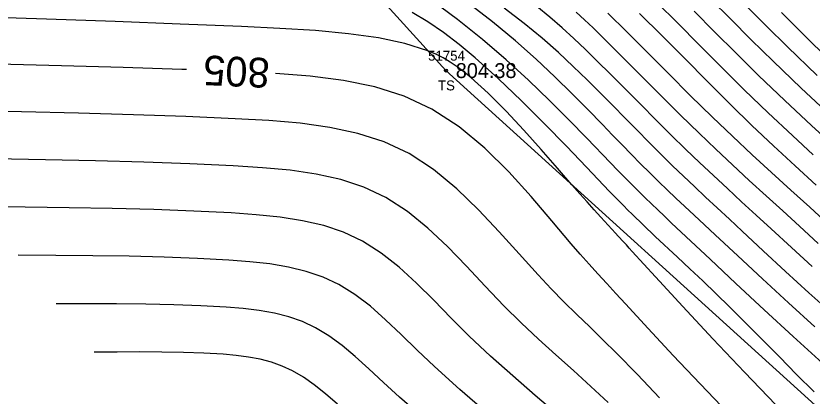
# Model space of a CAD drawing. Extents: x 1378535 to 1380697, y 997729 to 1000024.
# Drawn here: x 1379772.3 to 1379852.8, y 998705.8 to 998744.2 of the extents above; entities that cross this region are included whole.
import ezdxf

# ---------------------------------------------------------------- set-up
doc = ezdxf.new("R2010")
doc.units = 0
for name, color, linetype in [('RD_DTM_BkLn2', 7, 'Continuous'), ('RD_DTM_BkLn_txCode', 7, 'Continuous'), ('RD_DTM_Major1', 7, 'Continuous'), ('RD_DTM_Major1_Lbl', 7, 'Continuous'), ('RD_DTM_Minor1', 7, 'Continuous'), ('RD_EX_TX_Misc_ELEV', 7, 'Continuous'), ('RD_SMD_Locator', 7, 'Continuous')]:
    doc.layers.add(name, color=color, linetype=linetype)

msp = doc.modelspace()

# ---------------------------------------------------------------- linework, layer by layer
at = {"layer": 'RD_DTM_BkLn2'}
msp.add_lwpolyline([(1379855.611, 998702.628), (1379815.746, 998738.674), (1379770.168, 998788.836), (1379745.983, 998819.459), (1379725.877, 998843.791)], dxfattribs=at)
at = {"layer": 'RD_DTM_Major1'}
for points in [[(1379852.883, 998730.183), (1379850.774, 998732.118), (1379848.323, 998734.413), (1379845.901, 998736.737), (1379843.591, 998739.014), (1379841.35, 998741.263), (1379839.179, 998743.452), (1379837.08, 998745.549)], [(1379854.843, 998714.093), (1379852.439, 998716.234), (1379850.089, 998718.385), (1379847.829, 998720.486), (1379845.696, 998722.477), (1379844.411, 998723.672), (1379843.183, 998724.81), (1379842.004, 998725.906), (1379840.864, 998726.972), (1379839.753, 998728.023), (1379838.664, 998729.072), (1379837.463, 998730.251), (1379836.268, 998731.445), (1379835.07, 998732.656), (1379833.861, 998733.885), (1379832.63, 998735.135), (1379831.371, 998736.407), (1379830.036, 998737.737), (1379828.629, 998739.098), (1379827.119, 998740.498), (1379825.475, 998741.942), (1379823.664, 998743.438), (1379821.655, 998744.991)], [(1379789.535, 998738.772), (1379789.073, 998738.791), (1379783.125, 998738.99), (1379776.896, 998739.168), (1379770.455, 998739.331), (1379763.873, 998739.484), (1379757.22, 998739.632)], [(1379844.319, 998704.074), (1379841.446, 998707.047), (1379838.728, 998709.929), (1379836.199, 998712.651), (1379833.893, 998715.144), (1379832.931, 998716.181), (1379832.007, 998717.179), (1379831.108, 998718.157), (1379830.219, 998719.137), (1379829.326, 998720.14), (1379828.416, 998721.186), (1379826.458, 998723.502), (1379824.358, 998725.965), (1379822.106, 998728.449), (1379819.69, 998730.83), (1379817.102, 998732.984), (1379814.33, 998734.786), (1379811.532, 998736.082), (1379808.552, 998737.021), (1379805.383, 998737.671), (1379802.018, 998738.099), (1379798.526, 998738.369)], [(1379823.692, 998695.144), (1379820.778, 998697.523), (1379817.339, 998700.348), (1379814.05, 998703.107), (1379811.061, 998705.718), (1379809.455, 998707.186), (1379807.976, 998708.554), (1379806.587, 998709.807), (1379805.251, 998710.929), (1379803.93, 998711.905), (1379802.585, 998712.72), (1379801.263, 998713.335), (1379799.877, 998713.814), (1379798.421, 998714.178), (1379796.885, 998714.448), (1379795.261, 998714.645), (1379793.539, 998714.79), (1379790.986, 998714.938), (1379788.263, 998715.037), (1379785.405, 998715.097), (1379782.446, 998715.128), (1379779.42, 998715.139), (1379776.36, 998715.141)]]:
    msp.add_lwpolyline(points, dxfattribs=at)
at = {"layer": 'RD_DTM_Minor1'}
for points in [[(1379853.044, 998712.814), (1379850.367, 998715.238), (1379847.739, 998717.659), (1379845.242, 998719.982), (1379842.959, 998722.11), (1379841.873, 998723.121), (1379840.856, 998724.065), (1379839.899, 998724.956), (1379838.99, 998725.808), (1379838.118, 998726.634), (1379837.272, 998727.447), (1379836.348, 998728.352), (1379835.429, 998729.267), (1379834.504, 998730.202), (1379833.56, 998731.167), (1379832.584, 998732.171), (1379831.563, 998733.223), (1379830.098, 998734.731), (1379828.508, 998736.338), (1379826.772, 998738.035), (1379824.868, 998739.814), (1379822.776, 998741.668), (1379820.475, 998743.588), (1379817.087, 998746.213)], [(1379853.798, 998709.138), (1379850.848, 998711.818), (1379847.904, 998714.532), (1379845.07, 998717.171), (1379842.449, 998719.628), (1379838.554, 998723.289), (1379837.839, 998723.963), (1379837.164, 998724.604), (1379836.52, 998725.221), (1379835.896, 998725.826), (1379835.215, 998726.496), (1379834.535, 998727.174), (1379833.846, 998727.872), (1379833.134, 998728.6), (1379832.388, 998729.369), (1379829.984, 998731.86), (1379828.188, 998733.699), (1379826.222, 998735.661), (1379824.1, 998737.699), (1379821.838, 998739.768), (1379819.45, 998741.82), (1379816.928, 998743.832), (1379814.339, 998745.734)], [(1379854.598, 998734.172), (1379851.666, 998736.912), (1379848.833, 998739.625), (1379846.618, 998741.795), (1379844.522, 998743.883), (1379842.541, 998745.876)], [(1379852.961, 998706.231), (1379851.188, 998708.012), (1379849.452, 998709.77), (1379847.748, 998711.495), (1379846.075, 998713.179), (1379844.43, 998714.811), (1379843.053, 998716.15), (1379841.707, 998717.438), (1379840.406, 998718.668), (1379839.165, 998719.832), (1379836.917, 998721.935), (1379836.506, 998722.321), (1379836.109, 998722.696), (1379835.72, 998723.066), (1379835.338, 998723.432), (1379834.958, 998723.8), (1379834.577, 998724.173), (1379834.147, 998724.6), (1379833.706, 998725.043), (1379833.248, 998725.507), (1379832.77, 998725.997), (1379832.265, 998726.517), (1379831.729, 998727.074), (1379829.951, 998728.932), (1379827.924, 998731.041), (1379825.717, 998733.3), (1379823.399, 998735.607), (1379821.037, 998737.859), (1379818.7, 998739.956), (1379817.089, 998741.298), (1379815.506, 998742.509), (1379813.933, 998743.587), (1379812.35, 998744.531)], [(1379852.765, 998718.907), (1379850.665, 998720.831), (1379848.62, 998722.715), (1379847.113, 998724.097), (1379845.643, 998725.442), (1379844.204, 998726.764), (1379842.79, 998728.074), (1379841.394, 998729.384), (1379840.01, 998730.706), (1379838.478, 998732.204), (1379836.956, 998733.719), (1379835.443, 998735.24), (1379833.943, 998736.753), (1379832.456, 998738.246), (1379830.983, 998739.707), (1379829.847, 998740.814), (1379828.697, 998741.903), (1379827.512, 998742.981), (1379826.27, 998744.058), (1379824.948, 998745.141)], [(1379853.375, 998721.218), (1379851.475, 998722.964), (1379849.79, 998724.506), (1379848.104, 998726.045), (1379846.418, 998727.589), (1379844.731, 998729.147), (1379843.042, 998730.729), (1379841.351, 998732.343), (1379839.467, 998734.183), (1379837.597, 998736.041), (1379835.759, 998737.883), (1379833.972, 998739.675), (1379832.253, 998741.384), (1379830.622, 998742.976), (1379829.757, 998743.799), (1379828.912, 998744.582)], [(1379854.386, 998723.185), (1379852.522, 998724.875), (1379850.615, 998726.602), (1379848.674, 998728.371), (1379846.703, 998730.186), (1379844.709, 998732.051), (1379842.698, 998733.971), (1379840.452, 998736.168), (1379838.232, 998738.377), (1379836.079, 998740.538), (1379834.031, 998742.588), (1379832.129, 998744.466)], [(1379853.174, 998727.116), (1379851.039, 998729.062), (1379848.868, 998731.071), (1379846.682, 998733.136), (1379844.502, 998735.248), (1379842.189, 998737.556), (1379839.895, 998739.879), (1379837.608, 998742.186), (1379835.316, 998744.447)], [(1379855.401, 998730.676), (1379852.701, 998733.143), (1379850, 998735.663), (1379847.36, 998738.188), (1379845.083, 998740.42), (1379842.905, 998742.594), (1379840.827, 998744.684)], [(1379853.275, 998738.181), (1379850.285, 998741.066), (1379848.162, 998743.157), (1379846.167, 998745.151)], [(1379854.747, 998739.507), (1379851.661, 998742.537), (1379849.666, 998744.531)], [(1379849.108, 998704.938), (1379845.923, 998708.226), (1379842.742, 998711.591), (1379839.703, 998714.859), (1379836.94, 998717.859), (1379834.591, 998720.419), (1379834.283, 998720.754), (1379833.987, 998721.075), (1379833.702, 998721.385), (1379833.161, 998721.974), (1379832.903, 998722.254), (1379832.139, 998723.085), (1379831.422, 998723.867), (1379830.726, 998724.634), (1379830.024, 998725.415), (1379829.288, 998726.243), (1379828.493, 998727.149), (1379827.03, 998728.829), (1379825.393, 998730.696), (1379823.641, 998732.648), (1379821.831, 998734.581), (1379820.018, 998736.394), (1379818.261, 998737.983), (1379817.568, 998738.548), (1379816.88, 998739.061), (1379816.185, 998739.528), (1379815.469, 998739.95), (1379814.72, 998740.333), (1379813.925, 998740.679), (1379811.613, 998741.422), (1379808.933, 998741.985), (1379805.911, 998742.4), (1379802.576, 998742.704), (1379798.955, 998742.931), (1379795.075, 998743.118), (1379788.905, 998743.374), (1379782.312, 998743.619), (1379775.379, 998743.855), (1379768.191, 998744.084)], [(1379837.351, 998705.65), (1379835.099, 998707.993), (1379832.98, 998710.156), (1379831.618, 998711.503), (1379830.29, 998712.794), (1379828.983, 998714.06), (1379827.684, 998715.336), (1379826.381, 998716.653), (1379825.06, 998718.043), (1379823.142, 998720.164), (1379821.146, 998722.392), (1379819.054, 998724.623), (1379816.848, 998726.753), (1379814.51, 998728.679), (1379812.022, 998730.295), (1379809.516, 998731.468), (1379806.853, 998732.331), (1379804.023, 998732.939), (1379801.021, 998733.351), (1379797.837, 998733.625), (1379794.464, 998733.818), (1379789.473, 998734.037), (1379784.166, 998734.22), (1379778.607, 998734.374), (1379772.859, 998734.506), (1379766.985, 998734.624)], [(1379832.148, 998705.156), (1379830.397, 998706.791), (1379828.638, 998708.386), (1379826.874, 998709.969), (1379825.113, 998711.568), (1379823.361, 998713.212), (1379821.622, 998714.927), (1379819.735, 998716.904), (1379817.843, 998718.923), (1379815.919, 998720.906), (1379813.935, 998722.776), (1379811.861, 998724.455), (1379809.671, 998725.864), (1379807.47, 998726.898), (1379805.131, 998727.669), (1379802.648, 998728.223), (1379800.013, 998728.609), (1379797.218, 998728.873), (1379794.257, 998729.063), (1379789.872, 998729.272), (1379785.208, 998729.437), (1379780.32, 998729.567), (1379775.265, 998729.671), (1379770.099, 998729.758)], [(1379827.036, 998703.954), (1379824.769, 998705.893), (1379822.5, 998707.85), (1379820.27, 998709.836), (1379818.117, 998711.858), (1379816.293, 998713.68), (1379814.525, 998715.484), (1379812.778, 998717.218), (1379811.016, 998718.828), (1379809.205, 998720.261), (1379807.309, 998721.463), (1379805.409, 998722.353), (1379803.395, 998723.027), (1379801.258, 998723.522), (1379798.991, 998723.875), (1379796.588, 998724.123), (1379794.039, 998724.304), (1379790.263, 998724.498), (1379786.244, 998724.644), (1379782.029, 998724.751), (1379777.669, 998724.829), (1379773.211, 998724.888), (1379768.704, 998724.937)], [(1379819.904, 998704.102), (1379817.158, 998706.467), (1379814.587, 998708.792), (1379812.856, 998710.449), (1379811.225, 998712.038), (1379809.658, 998713.528), (1379808.114, 998714.887), (1379806.555, 998716.083), (1379804.942, 998717.085), (1379803.337, 998717.835), (1379801.642, 998718.41), (1379799.849, 998718.84), (1379797.95, 998719.154), (1379795.938, 998719.379), (1379793.804, 998719.545), (1379790.638, 998719.719), (1379787.266, 998719.843), (1379783.727, 998719.927), (1379780.065, 998719.981), (1379776.319, 998720.015), (1379772.532, 998720.039)], [(1379804.792, 998705.019), (1379803.585, 998706.042), (1379802.447, 998706.942), (1379801.348, 998707.717), (1379800.253, 998708.362), (1379799.197, 998708.852), (1379798.107, 998709.238), (1379796.975, 998709.535), (1379795.792, 998709.758), (1379794.549, 998709.923), (1379793.236, 998710.043), (1379791.292, 998710.161), (1379789.222, 998710.232), (1379787.051, 998710.267), (1379784.805, 998710.274), (1379782.509, 998710.263), (1379780.188, 998710.242)]]:
    msp.add_lwpolyline(points, dxfattribs=at)
at = {"layer": 'RD_SMD_Locator'}
msp.add_circle((1379815.746, 998738.674), 0.15, dxfattribs=at)

# ---------------------------------------------------------------- texts
at = {"layer": 'RD_DTM_BkLn_txCode'}
for s, p in [('51754', (1379813.951, 998739.674)), ('TS', (1379814.951, 998736.674))]:
    msp.add_text(s, height=1, dxfattribs=at).set_placement(p)
at = {"layer": 'RD_DTM_Major1_Lbl'}
msp.add_text('805', height=3, rotation=177.43179, dxfattribs=at).set_placement((1379797.993, 998739.916))
at = {"layer": 'RD_EX_TX_Misc_ELEV'}
msp.add_text('804.38', height=1.5, dxfattribs=at).set_placement((1379816.746, 998737.924))

doc.saveas('drawing.dxf')
